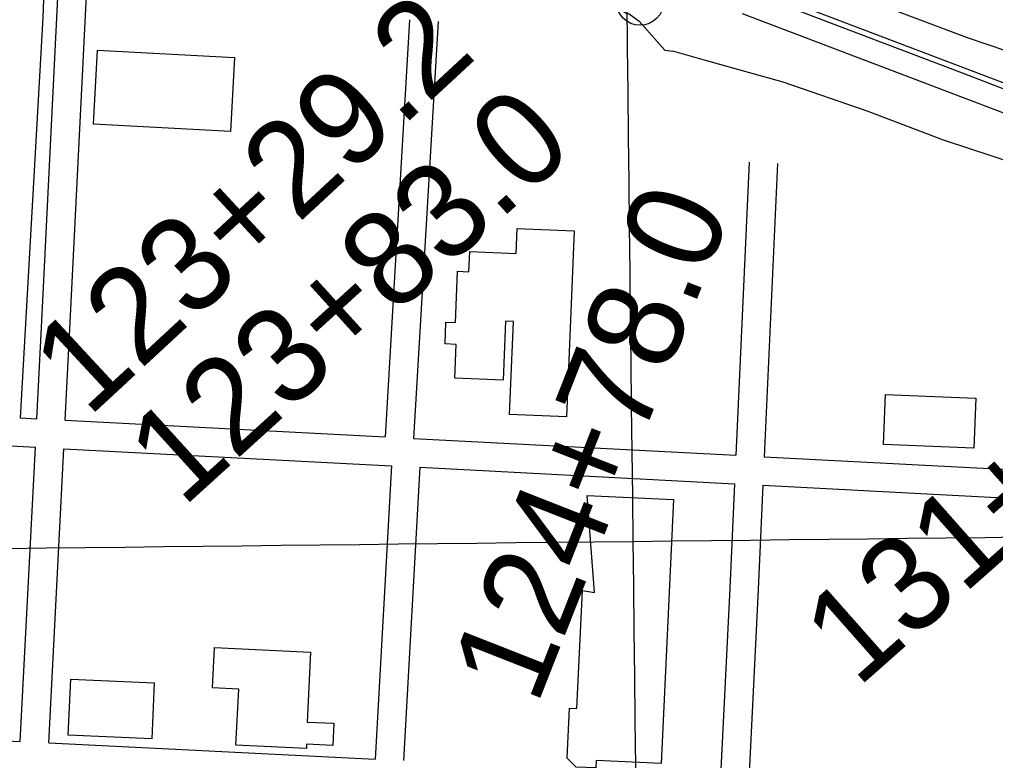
# Model space of a CAD drawing. Extents: x 3677843 to 3715951, y 511991 to 537744.
# Drawn here: x 3691875 to 3692904, y 529414 to 530195 of the extents above; entities that cross this region are included whole.
import ezdxf

# ---------------------------------------------------------------- set-up
doc = ezdxf.new("R2010")
doc.units = 0
for name, color, linetype in [('V-BLDG-OTLN', 7, 'Continuous'), ('V-FLOD-BASE', 7, 'Continuous'), ('V-GRID-MAJR', 7, 'Continuous'), ('V-LEVE-TOET', 7, 'Continuous'), ('V-ROAD-CNTR', 7, 'Continuous'), ('V-SURV-IDEN', 7, 'Continuous'), ('V-SURV-LINE', 7, 'Continuous')]:
    doc.layers.add(name, color=color, linetype=linetype)

msp = doc.modelspace()

# ---------------------------------------------------------------- linework, layer by layer
at = {"layer": 'V-BLDG-OTLN'}
for points in [[(3691957.608, 530162.675), (3692101.887, 530154.763), (3692097.6070000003, 530076.718), (3691953.328, 530084.629)], [(3692459.88, 529972.127), (3692451.878, 529776.061), (3692392.0130000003, 529778.505), (3692396.0130000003, 529876.469), (3692387.7430000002, 529876.807), (3692385.202, 529814.545), (3692334.2600000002, 529816.6240000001), (3692335.72, 529852.407), (3692323.952, 529852.886), (3692324.892, 529875.922), (3692334.929, 529875.512), (3692337.131, 529929.438), (3692349.149, 529928.949), (3692350.017, 529950.215), (3692398.86, 529948.224), (3692399.935, 529974.572)], [(3692788.395, 529799.517), (3692883.599, 529795.718), (3692881.489, 529742.917), (3692786.286, 529746.724)], [(3692564.795, 529688.796), (3692551.606, 529410.541), (3692483.254, 529413.783), (3692482.873, 529405.767), (3692462.026, 529406.756), (3692452.794, 529416.205), (3692455.282, 529468.698), (3692462.927, 529468.335), (3692468.858, 529592.9990000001), (3692481.488, 529590.871), (3692473.585, 529693.122)], [(3692182.132, 529527.995), (3692178.579, 529454.204), (3692206.794, 529452.844), (3692205.664, 529429.355), (3692177.983, 529430.689), (3692177.772, 529426.318), (3692103.497, 529429.8960000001), (3692106.336, 529488.805), (3692078.696, 529490.134), (3692080.756, 529532.88)], [(3691929.284, 529499.495), (3692017.3540000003, 529495.58), (3692014.72, 529436.362), (3691926.6520000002, 529440.277)]]:
    msp.add_lwpolyline(points, close=True, dxfattribs=at)
at = {"layer": 'V-FLOD-BASE'}
msp.add_lwpolyline([(3692564.561, 530225.593), (3692617.531, 530232.399), (3692622.6920000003, 530231.6900000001), (3692633.436, 530228.696), (3692704.3910000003, 530201.333), (3692876.578, 530136.008), (3693099.417, 530049.719), (3693230.958, 529999.179), (3693242.943, 529993.037), (3693250.5700000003, 529986.823), (3693260.646, 529976.292), (3693333.919, 529903.807), (3693406.435, 529829.332), (3693421.307, 529816.106), (3693429.3680000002, 529807.523), (3693436.204, 529801.297), (3693453.369, 529793.256), (3693566.254, 529745.186), (3693773.666, 529657.458), (3693857.453, 529620.399), (3693994.2800000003, 529561.628), (3694071.273, 529528.419), (3694164.227, 529487.947)], dxfattribs=at)
at = {"layer": 'V-GRID-MAJR'}
for points in [[(3692591.0047914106, 523584.97265147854), (3692522.254, 529644.703), (3692453.494, 535705.299), (3692453.4590000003, 535708.368)], [(3681966.5640000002, 529526.479), (3687244.413, 529585.207), (3692522.254, 529644.703), (3697800.0870000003, 529704.966), (3703077.91, 529765.996), (3708355.725, 529827.795), (3713633.5300000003, 529890.361), (3713633.531, 529890.361)]]:
    msp.add_spline(points, degree=3, dxfattribs=at)
at = {"layer": 'V-LEVE-TOET'}
for points in [[(3692382.369, 530334.778), (3692434.245, 530310.116), (3692493.752, 530286.1240000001), (3692524.435, 530273.49), (3692552.988, 530262.656), (3692580.382, 530258.3740000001), (3692604.628, 530253.776), (3692639.524, 530256.711), (3692670.838, 530253.805), (3692717.862, 530238.019), (3692769.724, 530215.742), (3692874.416, 530175.935), (3692936.503, 530154.878)], [(3692276.924, 530286.112), (3692291.299, 530280.3960000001), (3692309.245, 530274.735), (3692317.028, 530274.26), (3692333.637, 530277.506), (3692349.069, 530280.138), (3692357.984, 530280.879), (3692377.1, 530276.429), (3692448.97, 530248.441), (3692480.13, 530235.26), (3692484.958, 530231.172), (3692492.828, 530222.97), (3692497.694, 530216.502), (3692500.748, 530211.792), (3692504.96, 530208.884), (3692514, 530201.89), (3692518.184, 530200.767), (3692528.426, 530193.198), (3692555.704, 530162.697), (3692564.096, 530161.419)], [(3693321.721, 529800.599), (3693316.583, 529806.638), (3693306.103, 529820.917), (3693293.793, 529834.642), (3693274.134, 529864.011), (3693239.213, 529910.998), (3693216.849, 529929.024), (3693178.7460000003, 529945.482), (3693112.87, 529973.308), (3693060.585, 529989.535), (3692954.251, 530033.255), (3692849.381, 530067.805), (3692770.0700000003, 530097.778), (3692680.494, 530128.897), (3692598.411, 530151.732), (3692564.096, 530161.419)]]:
    msp.add_lwpolyline(points, dxfattribs=at)
at = {"layer": 'V-ROAD-CNTR'}
for points in [[(3691923.5431140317, 529772.3514290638), (3691929.1961027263, 529882.5702086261), (3691955.98904914, 530424.7711242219), (3691954.806051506, 530447.848078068), (3691947.447066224, 530455.6890623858), (3691941.968077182, 530462.5860485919), (3691922.928115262, 530478.5270167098), (3691801.557358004, 530546.6478804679), (3691604.9137512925, 530655.88666199), (3691530.8768993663, 530691.387590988), (3691227.842505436, 530808.63635649), (3691109.4957421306, 530875.548222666)], [(3691893.5841739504, 529773.9174259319), (3691899.23416265, 529884.0782056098), (3691925.9511092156, 530424.7431242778), (3691925.408110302, 530435.334103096), (3691924.7271116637, 530436.0611016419), (3691920.37412037, 530441.538090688), (3691905.8101494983, 530453.7330662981), (3691786.9313872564, 530520.4539328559), (3691591.1317788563, 530629.2247153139), (3691518.9609231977, 530663.8316460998), (3691214.978531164, 530781.4464108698), (3691094.729771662, 530849.434274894)], [(3690963.0260350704, 530640.5926925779), (3691567.6788257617, 530607.513758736), (3691594.135772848, 530606.0877615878), (3691618.6587238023, 530599.619774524), (3691633.763693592, 530588.7927961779), (3691875.0172110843, 530457.2960591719), (3691885.788189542, 530449.541074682), (3691893.6261738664, 530441.0810916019), (3691898.9581632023, 530430.8961119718), (3691901.641157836, 530419.876134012), (3691902.311156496, 530409.18715539), (3691904.513152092, 530393.3261871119), (3691906.142148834, 530371.8902299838), (3691899.722161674, 530197.0545796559), (3691875.992209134, 529774.8364240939)], [(3692286.54338803, 530194.6225845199), (3692260.79843952, 529754.736464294)], [(3692316.491328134, 530192.8705880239), (3692290.7573796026, 529753.172467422)], [(3692644.5296720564, 530044.6158845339), (3692630.3847003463, 529735.432502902)], [(3692674.49761212, 530043.245887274), (3692660.3446404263, 529733.8665060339)], [(3691262.2140294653, 529772.3985370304), (3691846.96426719, 529746.3114811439), (3691892.047177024, 529743.9574858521)], [(3691875.992209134, 529774.8364240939), (3691893.5841739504, 529773.9174259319)], [(3691923.5431140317, 529772.3524290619), (3692260.7974395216, 529754.736464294)], [(3692290.7563796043, 529753.1714674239), (3692630.383700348, 529735.4315029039)], [(3691876.1302088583, 529433.59410658), (3691892.048177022, 529743.9564858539)], [(3691906.09414893, 529432.1151095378), (3691922.0071171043, 529742.3914889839)], [(3691922.0061171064, 529742.392488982), (3692267.28342655, 529724.356525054)], [(3692660.343640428, 529733.8665060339), (3693074.3338124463, 529712.2425492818), (3693324.7063117, 529690.7995921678)], [(3692267.284426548, 529724.356525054), (3692250.279460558, 529415.122143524)], [(3692297.2433666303, 529722.792528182), (3692280.24340063, 529413.6441464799)], [(3692297.2433666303, 529722.791528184), (3692629.013703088, 529705.462562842)], [(3692629.013703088, 529705.46356284), (3692623.970713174, 529595.210783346), (3692614.3247324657, 529397.1491794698)], [(3692658.973643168, 529703.8975659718), (3692653.936653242, 529593.7947861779), (3692628.8007035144, 529077.675818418)], [(3692658.9726431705, 529703.8975659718), (3693072.2718165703, 529682.30860915), (3693322.1463168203, 529660.909651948)], [(3690938.7570836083, 529481.2120113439), (3691679.2306026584, 529443.316087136), (3691876.1302088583, 529433.5951065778)], [(3691906.093148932, 529432.1151095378), (3692250.279460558, 529415.122143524)]]:
    msp.add_lwpolyline(points, dxfattribs=at)
at = {"layer": 'V-SURV-LINE'}
for points in [[(3692648.155193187, 530228.9588554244), (3693224.1633175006, 530010.1286212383)], [(3693213.498130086, 529982.08840167), (3692637.4904387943, 530200.9184713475)]]:
    msp.add_lwpolyline(points, dxfattribs=at)
msp.add_circle((3692529.44098, 530213.86666), 25, dxfattribs=at)

# ---------------------------------------------------------------- texts
at = {"layer": 'V-SURV-IDEN'}
for s, height, rotation, p in [('123+29.2', 100, 42.8363888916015, (3691947.7281230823, 529774.2964985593)), ('123+83.0', 100, 42.24335742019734, (3692047.3582401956, 529679.280968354)), ('124+78.0', 99.99999999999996, 68.54750001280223, (3692420.6422638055, 529470.2871083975)), ('131+34.2', 99.99999999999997, 41.4992780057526, (3692758.680433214, 529489.2736744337))]:
    msp.add_text(s, height=height, rotation=rotation, dxfattribs=at).set_placement(p)

doc.saveas('drawing.dxf')
